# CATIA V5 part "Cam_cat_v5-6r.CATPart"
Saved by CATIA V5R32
Part number: Cam
Bounding box of the stored display mesh (mm): x -10 to 60, y -35 to 35, z -50 to 30
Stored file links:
  D:\PROJECTS\Project 2022\CATIA V5 6R 2022\Resources\Tutorial Files\c16_catia_v5_6r2022_tut\Cam Follower mechanism\Cam_cat_v5-6r.CATPart
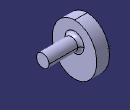
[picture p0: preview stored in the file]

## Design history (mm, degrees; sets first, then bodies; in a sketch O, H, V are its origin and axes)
Body1 (main body)
  Sketch1 on yz-plane, origin (0, 0, 0), H (0, 1, 0), V (0, 0, 1)
    point P1 (0, -10)
    ellipse A1 centre (0, -10) semi-axes 40, 35 rotation 90
    point P2 (0, 30)
    "Radius" A1 = 40
    distance V A1 = 35
    distance P1 H = 10
    coincidence: P1 V, P2 V, A1 P2
  Pad1: profile Sketch1, direction (1, 0, 0), length 10, mirrored extent
  Sketch2 on end face of Pad1, origin (10, 0, 0), H (0, 1, 0), V (0, 0, 1)
    circle A1 centre (0, 0) radius 10
    radius A1 = 10
  Pad2: profile Sketch2, direction (1, 0, 0), length 50
  Sketch3 on start face of Pad1, origin (-10, 0, 0), H (0, -1, 0), V (0, 0, 1)
    point P1 (-33.8886, 0)
    reference projected curve E1 from edge [start face of Pad1 | face of Pad1 from Sketch1.A1]
    coincidence: P1 H, P1 E1
  Fillet1: radius 5, on edge [end face of Pad1 | face of Pad2 from Sketch2.A1]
